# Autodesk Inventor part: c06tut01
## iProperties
Shininess: 77.0
Length Units: 11269
Angle Units: 11279
Time Units: 11290
Mass Units: 11283
Length Display Precision: 3
Angle Display Precision: 2
Created: 2002-02
Part Number: c06tut01
Document SubType Name: Modeling
Designer: ***
Density: 1 g/cm^3
Density: 0.0
Volumn: 0.0
Area: 0.0
PropertySet Name: Model Information
Control State: 0
Master: False
Checked Out: False
Author: ***
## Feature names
1. Extrusion1
2. Extrusion2
3. Extrusion3
4. Extrusion4
5. Extrusion5
6. Fillet2
7. Extrusion6
8. Hole1
